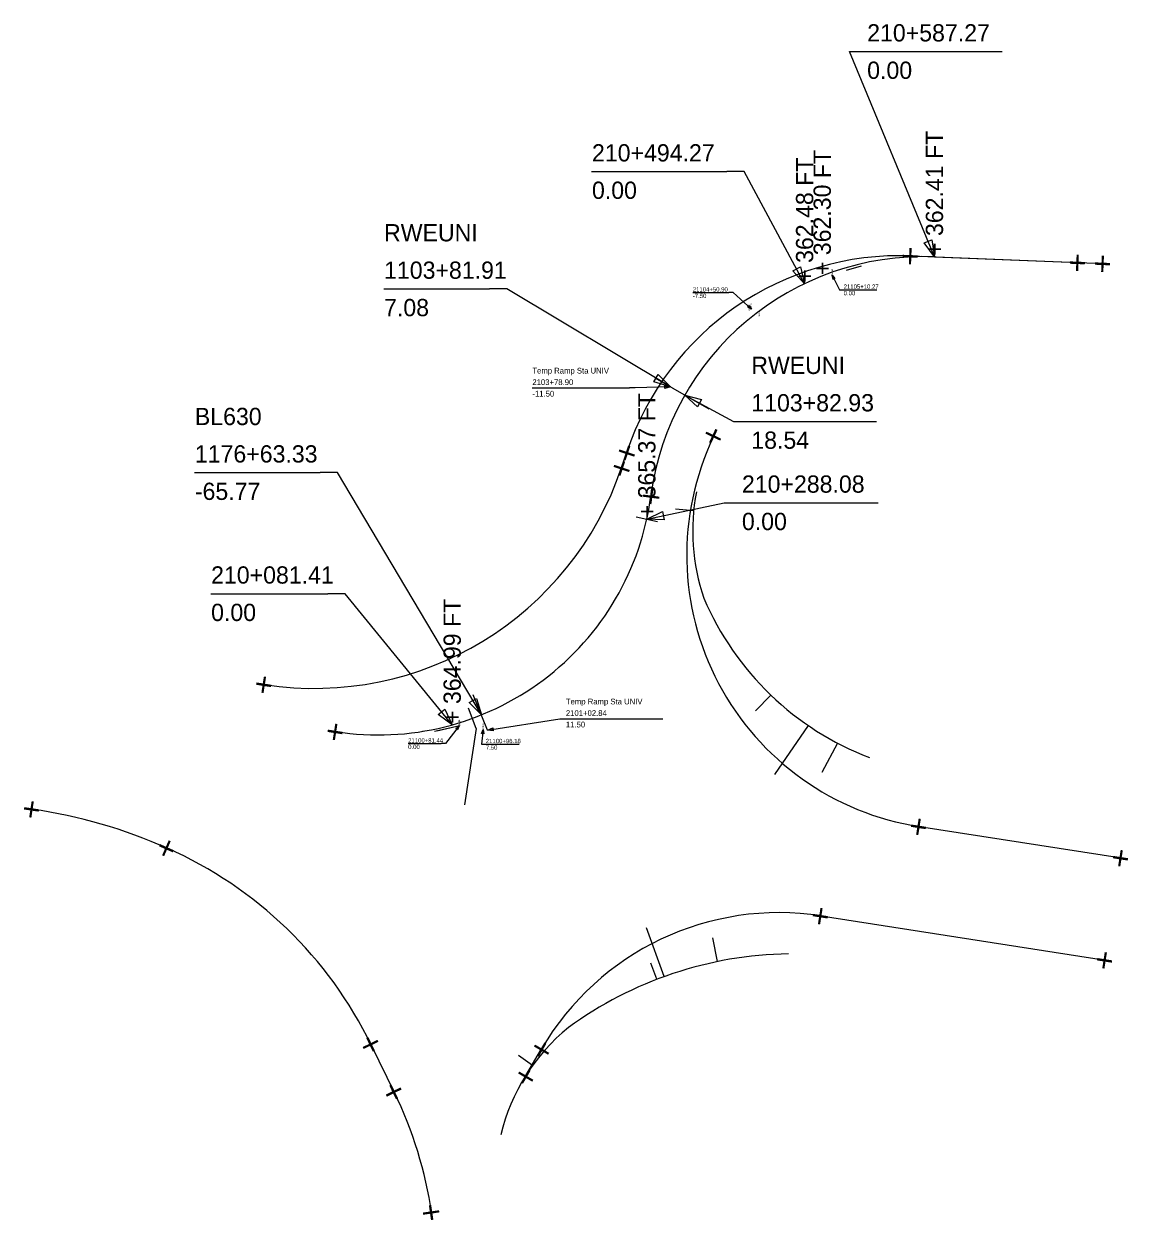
# Model space of a CAD drawing. Extents: x 1195880 to 1289360, y 2059330 to 2086925.
# Drawn here: x 1209064 to 1209831, y 2068612 to 2069443 of the extents above; entities that cross this region are included whole.
import ezdxf

# ---------------------------------------------------------------- set-up
doc = ezdxf.new("R2010")
doc.units = 0
for name, color, linetype in [('20', 7, 'Continuous'), ('5', 7, 'Continuous'), ('58', 7, 'Continuous'), ('9', 7, 'Continuous'), ('Anno', 7, 'Continuous'), ('Default', 7, 'Continuous'), ('Prop Ramp BL', 7, 'Continuous')]:
    doc.layers.add(name, color=color, linetype=linetype)

msp = doc.modelspace()

# ---------------------------------------------------------------- linework, layer by layer
for p, q in [((1209649.68, 2069423.9), (1209743.6, 2069423.9)), ((1209458.54, 2069340.51), (1209552.46, 2069340.51)), ((1209635.5, 2069271.99), (1209645.9, 2069275.02)), ((1209314.13, 2069258.98), (1209387.64, 2069258.98)), ((1209417.14, 2069190.13), (1209484.83, 2069190.13)), ((1209569.19, 2069166.84), (1209656.31, 2069166.84)), ((1209182.71, 2069131.31), (1209270.02, 2069131.31)), ((1209562.68, 2069110.34), (1209657.55, 2069110.34)), ((1209194, 2069047.16), (1209275.26, 2069047.16)), ((1209440.42, 2068960.22), (1209508.11, 2068960.22)), ((1209365.97, 2068955.1), (1209349.41, 2068951.33)), ((1209366.04, 2068955.15), (1209349.44, 2068951.34)), ((1209364.98, 2068954.82), (1209350.96, 2068951.66))]:
    msp.add_line(p, q)
for points in [[(1209696.64, 2069281.23), (1209637.68, 2069423.9), (1209649.68, 2069423.9)], [(1209606.47, 2069262.59), (1209564.46, 2069340.51), (1209552.46, 2069340.51)], [(1209513.3, 2069190.89), (1209399.64, 2069258.98), (1209387.64, 2069258.98)], [(1209513.3, 2069190.89), (1209488.83, 2069190.13), (1209484.83, 2069190.13)], [(1209523.29, 2069185.18), (1209557.19, 2069166.84), (1209569.19, 2069166.84)], [(1209381.94, 2068962.94), (1209282.02, 2069131.31), (1209270.02, 2069131.31)], [(1209496.87, 2069098.94), (1209550.68, 2069110.34), (1209562.68, 2069110.34)], [(1209361.66, 2068956.04), (1209287.26, 2069047.16), (1209275.26, 2069047.16)], [(1209386.25, 2068952.28), (1209436.42, 2068960.22), (1209440.42, 2068960.22)]]:
    msp.add_lwpolyline(points)
for points in [[(1209696.64, 2069281.23), (1209689.5, 2069290.88), (1209694.88, 2069293.1)], [(1209606.47, 2069262.59), (1209598.38, 2069271.45), (1209603.51, 2069274.22)], [(1209513.3, 2069190.89), (1209501.82, 2069194.38), (1209504.81, 2069199.37)], [(1209513.3, 2069190.89), (1209509.45, 2069189.8), (1209509.39, 2069191.74)], [(1209523.29, 2069185.18), (1209534.91, 2069182.2), (1209532.14, 2069177.08)], [(1209496.87, 2069098.94), (1209507.66, 2069104.2), (1209508.87, 2069098.51)], [(1209381.94, 2068962.94), (1209373.49, 2068971.47), (1209378.5, 2068974.44)], [(1209361.66, 2068956.04), (1209352.04, 2068963.21), (1209356.55, 2068966.9)], [(1209386.25, 2068952.28), (1209389.93, 2068953.84), (1209390.23, 2068951.93)]]:
    msp.add_lwpolyline(points, close=True)
at = {"layer": '20'}
for p, q in [((1209686.21, 2068885.33), (1209826.52, 2068863.51)), ((1209618.01, 2068823.24), (1209815.48, 2068792.53)), ((1209305.53, 2068733.52), (1209321.62, 2068700.4)), ((1209412.87, 2068712.26), (1209423.84, 2068730.99))]:
    msp.add_line(p, q, dxfattribs=at)
for centre, radius, start, end in [((1209715.55, 2069074.05), 190.99, 154.60186, 261.16171), ((1209017.01, 2068538.76), 362.6, 66.10643, 81.5718), ((1209047.84, 2068608.35), 286.48, 25.90831, 66.10643), ((1209588.66, 2068634.52), 190.99, 81.16171, 149.65978), ((1209063.93, 2068575.23), 286.48, 8.3004, 25.92964)]:
    msp.add_arc(centre, radius, start, end, dxfattribs=at)
at = {"layer": '5'}
for p, q in [((1209680.48, 2069281.87), (1209814.04, 2069276.59)), ((1209696.64, 2069281.23), (1209796.56, 2069277.28)), ((1209479.35, 2069134.87), (1209482.94, 2069145.58))]:
    msp.add_line(p, q, dxfattribs=at)
for centre, radius, start, end in [((1209672.57, 2069082.03), 200, 87.73445, 161.47307), ((1209689.09, 2069090.4), 190.99, 87.73445, 172.53796), ((1209689.09, 2069090.4), 190.99, 87.73445, 172.53796), ((1209266.01, 2069206.37), 225, 261.16171, 341.47307), ((1209310.35, 2069140), 190.99, 261.16171, 352.53778), ((1209310.35, 2069140), 190.99, 261.16171, 352.53778)]:
    msp.add_arc(centre, radius, start, end, dxfattribs=at)
at = {"layer": 'Anno'}
for p, q in [((1209528.83, 2069256.34), (1209553.8, 2069256.34)), ((1209633.6, 2069258.29), (1209656.61, 2069258.29)), ((1209331.11, 2068942.96), (1209354.11, 2068942.96)), ((1209385.04, 2068942.55), (1209408.18, 2068942.55))]:
    msp.add_line(p, q, dxfattribs=at)
for points in [[(1209625.63, 2069268.49), (1209630.6, 2069258.29), (1209633.6, 2069258.29)], [(1209569.67, 2069244.85), (1209556.8, 2069256.34), (1209553.8, 2069256.34)], [(1209366.61, 2068955.28), (1209357.11, 2068942.96), (1209354.11, 2068942.96)], [(1209383.22, 2068952.74), (1209382.04, 2068942.55), (1209385.04, 2068942.55)]]:
    msp.add_lwpolyline(points, dxfattribs=at)
for points in [[(1209625.63, 2069268.49), (1209627.56, 2069266.2), (1209626.25, 2069265.56)], [(1209569.67, 2069244.85), (1209567.01, 2069246.25), (1209567.98, 2069247.33)], [(1209366.61, 2068955.28), (1209365.41, 2068952.53), (1209364.26, 2068953.42)], [(1209383.22, 2068952.74), (1209383.61, 2068949.77), (1209382.16, 2068949.94)]]:
    msp.add_lwpolyline(points, close=True, dxfattribs=at)
at = {"layer": 'Default'}
for p, q in [((1209502.52, 2069197.05), (1209539.96, 2069175.65)), ((1209529.43, 2069104.7), (1209516.74, 2069105.91)), ((1209489.54, 2069100.52), (1209504.21, 2069097.36)), ((1209386.25, 2068952.28), (1209376.28, 2068976.95)), ((1209582.94, 2068976.76), (1209572.36, 2068965.75)), ((1209378.27, 2068953.5), (1209373.14, 2068967.59)), ((1209378.27, 2068953.5), (1209370.16, 2068900.48)), ((1209378.23, 2068953.49), (1209378.31, 2068953.51)), ((1209608.9, 2068955.63), (1209585.48, 2068921.49)), ((1209629.24, 2068943.35), (1209618.48, 2068922.93)), ((1209686.21, 2068885.33), (1209826.52, 2068863.51)), ((1209618.01, 2068823.24), (1209815.48, 2068792.53)), ((1209508.91, 2068781.06), (1209496.66, 2068814.9)), ((1209546.04, 2068791.52), (1209542.66, 2068808.01)), ((1209503.89, 2068779.19), (1209499.6, 2068790.35)), ((1209417.56, 2068719.3), (1209407.78, 2068726.33)), ((1209412.87, 2068712.26), (1209423.84, 2068730.99))]:
    msp.add_line(p, q, dxfattribs=at)
for centre, radius, start, end in [((1209715.55, 2069074.05), 190.99, 154.60186, 261.16171), ((1209674.22, 2069090.89), 145.45, 169.26757, 198.79871), ((1209724.48, 2069124.07), 204.29, 203.07057, 249.07572), ((1209588.66, 2068634.52), 190.99, 81.16171, 149.65978), ((1209599.54, 2068530.56), 266.39, 90.92133, 126.14637), ((1209528.98, 2068639.2), 137.23, 129.11296, 166.56302)]:
    msp.add_arc(centre, radius, start, end, dxfattribs=at)
at = {"layer": 'Prop Ramp BL'}
for centre, start, end in [((1209689.09, 2069090.4), 87.73445, 172.53796), ((1209310.35, 2069140), 261.16171, 352.53778)]:
    msp.add_arc(centre, 190.99, start, end, dxfattribs=at)

# ---------------------------------------------------------------- texts
for s, height, rotation, p in [(' 362.40', 1, 90, (1209626.14, 2069268.18)), ('10.84     0.73%', 0.14, 16.22089, (1209639.79, 2069273.38)), (' 362.73', 1, 90, (1209568.46, 2069243.41)), (' 362.76', 1, 90, (1209569.67, 2069244.12)), (' 363.56', 1, 90, (1209575.42, 2069239.4)), (' 365.04', 1, 90, (1209367.01, 2068954.92)), (' 365.04', 1, 90, (1209367.31, 2068954.96)), (' 365.21', 1, 90, (1209383.68, 2068952.56)), ('16.98     -0.80%', 0.14, 12.84045, (1209356.72, 2068953.14)), ('14.38     -0.89%', 0.14, 12.71444, (1209357, 2068953.17))]:
    msp.add_text(s, height=height, rotation=rotation).set_placement(p)
at = {"layer": '20'}
for s, height, p in [('210+587.27', 12, (1209649.93, 2069430.9)), ('0.00', 12, (1209649.93, 2069404.9)), ('210+494.27', 12, (1209458.79, 2069347.51)), ('0.00', 12, (1209458.79, 2069321.51)), ('RWEUNI', 12, (1209314.38, 2069291.98)), ('1103+81.91', 12, (1209314.38, 2069265.98)), ('7.08', 12, (1209314.38, 2069239.98)), ('RWEUNI', 12, (1209569.44, 2069199.84)), ('Temp Ramp Sta UNIV', 4, (1209417.39, 2069200.13)), ('2103+78.90', 4, (1209417.39, 2069192.13)), ('-11.50', 4, (1209417.39, 2069184.13)), ('1103+82.93', 12, (1209569.44, 2069173.84)), ('BL630', 12, (1209182.96, 2069164.31)), ('18.54', 12, (1209569.44, 2069147.84)), ('1176+63.33', 12, (1209182.96, 2069138.31)), ('-65.77', 12, (1209182.96, 2069112.31)), ('210+288.08', 12, (1209562.93, 2069117.34)), ('0.00', 12, (1209562.93, 2069091.34)), ('210+081.41', 12, (1209194.25, 2069054.16)), ('0.00', 12, (1209194.25, 2069028.16)), ('Temp Ramp Sta UNIV', 4, (1209440.67, 2068970.22)), ('2101+02.84', 4, (1209440.67, 2068962.22)), ('11.50', 4, (1209440.67, 2068954.22))]:
    msp.add_text(s, height=height, dxfattribs=at).set_placement(p)
for rotation, p in [(357.73445, (1209673.31, 2069274.15)), (357.73445, (1209789.39, 2069269.56)), (357.73445, (1209806.87, 2069268.87)), (244.60186, (1209538.74, 2069165.59)), (71.47307, (1209488.35, 2069136.54)), (71.47307, (1209484.76, 2069125.83)), (82.53778, (1209506.76, 2069107.36)), (82.53796, (1209506.76, 2069107.36)), (82.53778, (1209506.76, 2069107.36)), (82.53796, (1209506.76, 2069107.36)), (351.16171, (1209223.44, 2068977.19)), (351.16171, (1209273.01, 2068944.43)), (351.16171, (1209273.01, 2068944.43)), (351.5718, (1209062.2, 2068890.53)), (351.16171, (1209678.2, 2068878.48)), (336.10643, (1209154.37, 2068865.74)), (351.16171, (1209818.51, 2068856.66)), (351.16171, (1209610, 2068816.39)), (351.16171, (1209807.48, 2068785.68)), (295.90831, (1209295.34, 2068736.2)), (59.65978, (1209427.28, 2068721.03)), (59.65978, (1209416.31, 2068702.3)), (295.92964, (1209311.38, 2068703.17)), (295.90831, (1209311.43, 2068703.08)), (278.3004, (1209338.5, 2068622.22))]:
    msp.add_text('+', height=16, rotation=rotation, dxfattribs=at).set_placement(p)
at = {"layer": '58'}
for s, p in [(' +G.L. 363.25', (1209506.36, 2069194.63)), (' +G.L. 364.99', (1209360.79, 2068956.22)), (' +G.L. 364.68', (1209280.24, 2068951.52)), (' +G.L. 364.67', (1209298.63, 2068949.57)), (' +G.L. 364.74', (1209330.8, 2068950.41)), (' +G.L. 364.86', (1209340.81, 2068951.86)), (' +G.L. 364.92', (1209353.12, 2068954.29))]:
    msp.add_text(s, height=0.08, dxfattribs=at).set_placement(p)
at = {"layer": '9'}
for s, p in [(' + 362.41 FT', (1209702.64, 2069277.39)), (' + 362.30 FT', (1209624.69, 2069264.1)), (' + 362.48 FT', (1209612.47, 2069258.75)), (' + 365.37 FT', (1209502.87, 2069095.1)), (' + 364.99 FT', (1209367.69, 2068952.19))]:
    msp.add_text(s, height=12, rotation=90, dxfattribs=at).set_placement(p)
at = {"layer": 'Anno'}
for s, p in [('-7.50', (1209528.83, 2069252.59)), ('21104+50.90', (1209528.83, 2069257.09)), ('0.00', (1209633.6, 2069254.54)), ('21105+10.27', (1209633.6, 2069259.04)), ('0.00', (1209331.11, 2068939.21)), ('21100+81.44', (1209331.11, 2068943.71)), ('21100+96.18', (1209385.04, 2068943.3)), ('7.50', (1209385.04, 2068938.8))]:
    msp.add_text(s, height=3, dxfattribs=at).set_placement(p)

doc.saveas('drawing.dxf')
